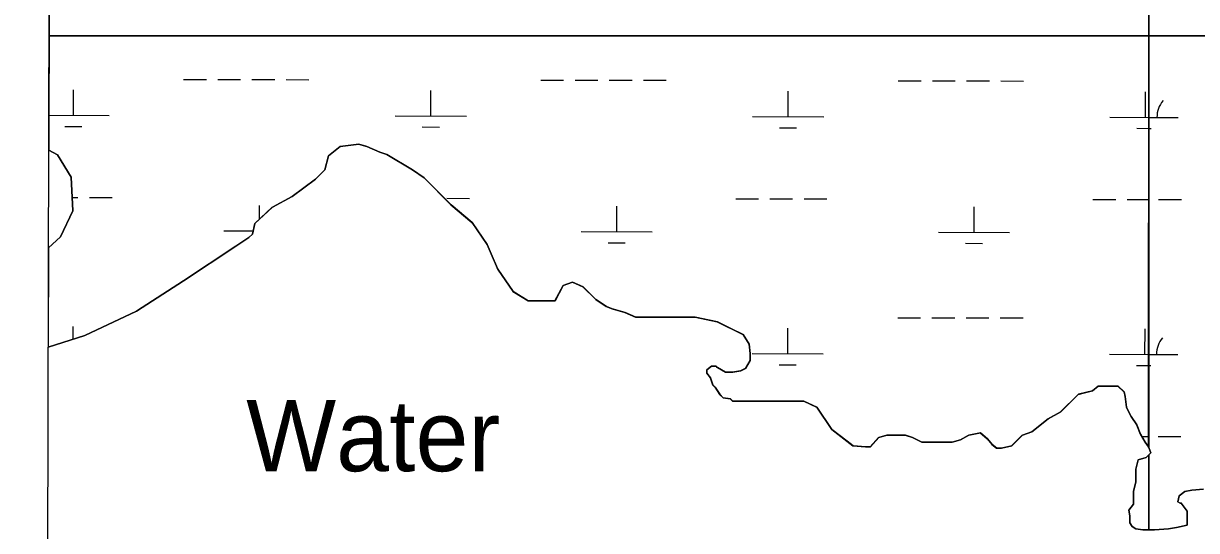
# Model space of a CAD drawing. Extents: x 3192952 to 3230831, y 849296 to 874698.
# Drawn here: x 3197144 to 3198792, y 869423 to 870134 of the extents above; entities that cross this region are included whole.
import ezdxf

# ---------------------------------------------------------------- set-up
doc = ezdxf.new("R2010")
doc.units = 0
for name, color, linetype in [('V-GRID-FRAM', 7, 'Continuous'), ('V-RIVR-IDEN', 7, 'Continuous'), ('V-SITE-VEGE', 7, 'Continuous'), ('V-TOPO-SHOR', 7, 'Continuous'), ('V-WETL-SWMP', 7, 'Continuous')]:
    doc.layers.add(name, color=color, linetype=linetype)

msp = doc.modelspace()

# ---------------------------------------------------------------- linework, layer by layer
at = {"layer": 'V-GRID-FRAM'}
msp.add_lwpolyline([(3197186.7, 872920.9), (3228554.1, 872861.6), (3228527.7, 854674), (3197144.3, 854733.3), (3197186.7, 872920.9)], dxfattribs=at)
at = {"layer": 'V-SITE-VEGE'}
for p, q in [((3197182.1, 870941.7), (3197180.1, 870116.9)), ((3197180.1, 870116.9), (3197179.8, 869956.4)), ((3197180.1, 870116.9), (3202799.6, 870116.9)), ((3199651, 870116.9), (3197180.1, 870116.9)), ((3197572.6, 869948.6), (3197589, 869961.7)), ((3197589, 869961.7), (3197615.3, 869965)), ((3197615.3, 869965), (3197626.8, 869961.7)), ((3197626.8, 869961.7), (3197644.8, 869953.5)), ((3197179.8, 869956.4), (3197192.1, 869950.1)), ((3197192.1, 869950.1), (3197211.1, 869918.7)), ((3197567.7, 869928.9), (3197572.6, 869948.6)), ((3197644.8, 869953.5), (3197654.7, 869950.2)), ((3197654.7, 869950.2), (3197690.8, 869928.9)), ((3197554.6, 869915.8), (3197567.7, 869928.9)), ((3197690.8, 869928.9), (3197707.2, 869917.4)), ((3197211.1, 869918.7), (3197213.6, 869871.1)), ((3197521.7, 869891.2), (3197554.6, 869915.8)), ((3197707.2, 869917.4), (3197744.9, 869879.7)), ((3197493.9, 869876.4), (3197521.7, 869891.2)), ((3197744.9, 869879.7), (3197774.4, 869855)), ((3197213.6, 869871.1), (3197196.4, 869834.9)), ((3197469.2, 869853.4), (3197493.9, 869876.4)), ((3197466, 869838.6), (3197469.2, 869853.4)), ((3197774.4, 869855), (3197795.8, 869823.9)), ((3197196.4, 869834.9), (3197179.4, 869819.4)), ((3197442.4, 869821.6), (3197461, 869833.7)), ((3197461, 869833.7), (3197466, 869838.6)), ((3197179.4, 869819.4), (3197179.1, 869680)), ((3197369.2, 869773.1), (3197442.4, 869821.6)), ((3197795.8, 869823.9), (3197804, 869804.2)), ((3197804, 869804.2), (3197810.5, 869789.4)), ((3197810.5, 869789.4), (3197831.9, 869758.2)), ((3197303.3, 869730.4), (3197369.2, 869773.1)), ((3197890.9, 869745.1), (3197902.4, 869766.4)), ((3197902.4, 869766.4), (3197915.6, 869771.3)), ((3197915.6, 869771.3), (3197930.3, 869764.8)), ((3197930.3, 869764.8), (3197948.4, 869746.7)), ((3197831.9, 869758.2), (3197853.2, 869745.1)), ((3197948.4, 869746.7), (3197963.1, 869736.9)), ((3197230.6, 869696.1), (3197303.3, 869730.4)), ((3197853.2, 869745.1), (3197890.9, 869745.1)), ((3197963.1, 869736.9), (3197971.3, 869733.6)), ((3197971.3, 869733.6), (3197989.4, 869728.7)), ((3197989.4, 869728.7), (3198004.2, 869722.1)), ((3198004.2, 869722.1), (3198087.8, 869722.1)), ((3198087.8, 869722.1), (3198119, 869715.5)), ((3198119, 869715.5), (3198155.1, 869697.5)), ((3197179.1, 869680), (3197230.6, 869696.1)), ((3198155.1, 869697.5), (3198163.3, 869684.3)), ((3198163.3, 869684.3), (3198165, 869671.2)), ((3198165, 869671.2), (3198165, 869661.4)), ((3198110.8, 869653.2), (3198104.3, 869648.2)), ((3198104.3, 869648.2), (3198104.3, 869643.3)), ((3198117.4, 869653.2), (3198110.8, 869653.2)), ((3198119, 869651.5), (3198117.4, 869653.2)), ((3198130.5, 869644.9), (3198119, 869651.5)), ((3198151.8, 869646.6), (3198140.4, 869644.9)), ((3198158.4, 869649.9), (3198151.8, 869646.6)), ((3198165, 869661.4), (3198158.4, 869649.9)), ((3198104.3, 869643.3), (3198109.2, 869636.7)), ((3198109.2, 869636.7), (3198112.5, 869626.9)), ((3198140.4, 869644.9), (3198130.5, 869644.9)), ((3198112.5, 869626.9), (3198115.7, 869623.6)), ((3198115.7, 869623.6), (3198122.3, 869613.8)), ((3198122.3, 869613.8), (3198127.2, 869608.8)), ((3198601.4, 869589.1), (3198626.1, 869613.8)), ((3198626.1, 869613.8), (3198645.7, 869618.7)), ((3198645.7, 869618.7), (3198653.9, 869625.2)), ((3198653.9, 869625.2), (3198681.8, 869625.2)), ((3198681.8, 869625.2), (3198690, 869617)), ((3198690, 869617), (3198691.7, 869610.5)), ((3198127.2, 869608.8), (3198137.1, 869607.2)), ((3198137.1, 869607.2), (3198140.4, 869603.9)), ((3198140.4, 869603.9), (3198240.4, 869603.9)), ((3198240.4, 869603.9), (3198258.5, 869595.7)), ((3198691.7, 869610.5), (3198693.3, 869595.7)), ((3198258.5, 869595.7), (3198265.1, 869585.9)), ((3198265.1, 869585.9), (3198273.3, 869574.4)), ((3198583.4, 869579.3), (3198601.4, 869589.1)), ((3198693.3, 869595.7), (3198699.9, 869582.6)), ((3198699.9, 869582.6), (3198708.1, 869571.1)), ((3198273.3, 869574.4), (3198279.8, 869564.5)), ((3198279.8, 869564.5), (3198301.2, 869548.1)), ((3198560.4, 869561.2), (3198583.4, 869579.3)), ((3198708.1, 869571.1), (3198713, 869557.9)), ((3198301.2, 869548.1), (3198309.4, 869541.5)), ((3198334, 869539.9), (3198345.5, 869553)), ((3198345.5, 869553), (3198357, 869556.3)), ((3198357, 869556.3), (3198383.2, 869556.3)), ((3198383.2, 869556.3), (3198393.1, 869553)), ((3198393.1, 869553), (3198406.2, 869546.5)), ((3198448.8, 869546.5), (3198460.3, 869549.7)), ((3198460.3, 869549.7), (3198471.8, 869556.3)), ((3198471.8, 869556.3), (3198488.2, 869559.6)), ((3198488.2, 869559.6), (3198498.1, 869551.4)), ((3198498.1, 869551.4), (3198504.6, 869543.2)), ((3198532.5, 869541.5), (3198547.3, 869556.3)), ((3198547.3, 869556.3), (3198560.4, 869561.2)), ((3198713, 869557.9), (3198719.6, 869546.5)), ((3198309.4, 869541.5), (3198327.4, 869539.9)), ((3198327.4, 869539.9), (3198334, 869539.9)), ((3198406.2, 869546.5), (3198448.8, 869546.5)), ((3198504.6, 869543.2), (3198511.2, 869538.3)), ((3198511.2, 869538.3), (3198517.8, 869538.3)), ((3198517.8, 869538.3), (3198532.5, 869541.5)), ((3198719.6, 869546.5), (3198724.5, 869539.9)), ((3198727.8, 869531.7), (3198721.2, 869525.1)), ((3198724.5, 869539.9), (3198727.8, 869531.7)), ((3198709.7, 869521.8), (3198706.5, 869508.7)), ((3198721.2, 869525.1), (3198709.7, 869521.8)), ((3198706.5, 869508.7), (3198706.5, 869490.7)), ((3198706.5, 869490.7), (3198703.2, 869477.5)), ((3198703.2, 869477.5), (3198703.2, 869459.5)), ((3198765.5, 869462.7), (3198767.2, 869471)), ((3198767.2, 869471), (3198775.4, 869477.5)), ((3198775.4, 869477.5), (3198785.2, 869479.2)), ((3198785.2, 869479.2), (3198801.6, 869480.8)), ((3198703.2, 869459.5), (3198696.6, 869451.3)), ((3198696.6, 869451.3), (3198698.3, 869443.1)), ((3198768.8, 869461.1), (3198765.5, 869462.7)), ((3198770.4, 869461.1), (3198768.8, 869461.1)), ((3198778.7, 869449.6), (3198770.4, 869461.1)), ((3198778.7, 869429.9), (3198778.7, 869449.6)), ((3198698.3, 869443.1), (3198698.3, 869433.2)), ((3198698.3, 869433.2), (3198701.5, 869428.3)), ((3198701.5, 869428.3), (3198706.5, 869425)), ((3198706.5, 869425), (3198716.3, 869423.4)), ((3198716.3, 869423.4), (3198732.7, 869423.4)), ((3198732.7, 869423.4), (3198752.4, 869425)), ((3198752.4, 869425), (3198763.9, 869426.6)), ((3198763.9, 869426.6), (3198778.7, 869429.9))]:
    msp.add_line(p, q, dxfattribs=at)
at = {"layer": 'V-TOPO-SHOR'}
for points in [[(3198046.8, 869722.1), (3198023.9, 869722.1), (3198004.2, 869722.1), (3197989.4, 869728.7), (3197971.3, 869733.6), (3197963.1, 869736.9), (3197948.4, 869746.7), (3197930.3, 869764.8), (3197915.6, 869771.3), (3197902.4, 869766.4), (3197890.9, 869745.1), (3197871.3, 869745.1), (3197853.2, 869745.1), (3197831.9, 869758.2), (3197810.5, 869789.4), (3197804, 869804.2), (3197795.8, 869823.9), (3197774.4, 869855), (3197744.9, 869879.7), (3197707.2, 869917.4), (3197690.8, 869928.9), (3197654.7, 869950.2), (3197644.8, 869953.5), (3197626.8, 869961.7), (3197615.3, 869965), (3197589, 869961.7), (3197572.6, 869948.6), (3197567.7, 869928.9), (3197554.6, 869915.8), (3197521.7, 869891.2), (3197493.9, 869876.4), (3197469.2, 869853.4), (3197466, 869838.6), (3197461, 869833.7), (3197442.4, 869821.6)], [(3197179.4, 869819.4), (3197196.4, 869834.9), (3197213.6, 869871.1), (3197211.1, 869918.7), (3197192.1, 869950.1), (3197179.8, 869956.4)], [(3197442.4, 869821.6), (3197369.2, 869773.1), (3197303.3, 869730.4), (3197230.6, 869696.1), (3197179.1, 869680)], [(3198785.2, 869479.2), (3198775.4, 869477.5), (3198767.2, 869471), (3198765.5, 869462.7), (3198768.8, 869461.1), (3198770.4, 869461.1), (3198778.7, 869449.6), (3198778.7, 869443.1), (3198778.7, 869429.9), (3198763.9, 869426.6), (3198752.4, 869425), (3198732.7, 869423.4), (3198716.3, 869423.4), (3198706.5, 869425), (3198701.5, 869428.3), (3198698.3, 869433.2), (3198698.3, 869443.1), (3198696.6, 869451.3), (3198703.2, 869459.5), (3198703.2, 869477.5), (3198706.5, 869490.7), (3198706.5, 869508.7), (3198709.7, 869521.8), (3198721.2, 869525.1), (3198727.8, 869531.7), (3198724.5, 869539.9), (3198719.6, 869546.5), (3198713, 869557.9), (3198708.1, 869571.1), (3198699.9, 869582.6), (3198693.3, 869595.7), (3198691.7, 869610.5), (3198690, 869617), (3198681.8, 869625.2), (3198673.6, 869625.2), (3198653.9, 869625.2), (3198645.7, 869618.7), (3198626.1, 869613.8), (3198601.4, 869589.1), (3198583.4, 869579.3), (3198560.4, 869561.2), (3198547.3, 869556.3), (3198532.5, 869541.5), (3198517.8, 869538.3), (3198511.2, 869538.3), (3198504.6, 869543.2), (3198498.1, 869551.4), (3198488.2, 869559.6), (3198471.8, 869556.3), (3198460.3, 869549.7), (3198448.8, 869546.5), (3198430.8, 869546.5), (3198417.7, 869546.5), (3198406.2, 869546.5), (3198393.1, 869553), (3198383.2, 869556.3), (3198366.8, 869556.3), (3198357, 869556.3), (3198345.5, 869553), (3198334, 869539.9), (3198327.4, 869539.9), (3198309.4, 869541.5), (3198301.2, 869548.1), (3198279.8, 869564.5), (3198273.3, 869574.4), (3198265.1, 869585.9), (3198258.5, 869595.7), (3198240.4, 869603.9), (3198230.6, 869603.9), (3198215.8, 869603.9), (3198204.3, 869603.9), (3198191.2, 869603.9), (3198183, 869603.9), (3198163.3, 869603.9), (3198156.8, 869603.9), (3198148.6, 869603.9), (3198140.4, 869603.9), (3198137.1, 869607.2), (3198127.2, 869608.8), (3198122.3, 869613.8), (3198115.7, 869623.6), (3198112.5, 869626.9), (3198109.2, 869636.7), (3198104.3, 869643.3), (3198104.3, 869648.2), (3198110.8, 869653.2), (3198117.4, 869653.2), (3198119, 869651.5), (3198130.5, 869644.9), (3198140.4, 869644.9), (3198151.8, 869646.6), (3198158.4, 869649.9), (3198165, 869661.4), (3198165, 869671.2), (3198163.3, 869684.3), (3198155.1, 869697.5), (3198138.7, 869705.7), (3198119, 869715.5), (3198087.8, 869722.1), (3198064.9, 869722.1), (3198046.8, 869722.1)], [(3198801.6, 869480.8), (3198785.2, 869479.2)]]:
    msp.add_lwpolyline(points, dxfattribs=at)
at = {"layer": 'V-WETL-SWMP'}
for p, q in [((3197182.1, 870941.7), (3197179.8, 869956.4)), ((3198724.4, 869538.9), (3198725.1, 870637.6)), ((3198724.9, 870637.5), (3198724.9, 869538.9)), ((3197369.2, 870055.8), (3197401.2, 870055.7)), ((3197417.2, 870055.7), (3197449.2, 870055.6)), ((3197465.2, 870055.6), (3197497.2, 870055.5)), ((3197513.2, 870055.5), (3197545.2, 870055.4)), ((3197871.1, 870054.8), (3197903, 870054.8)), ((3197919, 870054.7), (3197951, 870054.7)), ((3197967, 870054.6), (3197999, 870054.6)), ((3198015, 870054.6), (3198047, 870054.5)), ((3198372.9, 870053.9), (3198404.9, 870053.8)), ((3198420.9, 870053.8), (3198452.9, 870053.7)), ((3198468.9, 870053.7), (3198500.9, 870053.6)), ((3198516.9, 870053.6), (3198548.9, 870053.5)), ((3197214.6, 870005.3), (3197214.6, 870041.3)), ((3197716.4, 870004.4), (3197716.5, 870040.4)), ((3198218.2, 870003.4), (3198218.3, 870039.4)), ((3198720.1, 870002.5), (3198720.1, 870038.5)), ((3197179.9, 870005.4), (3197264.6, 870005.2)), ((3197666.4, 870004.5), (3197766.4, 870004.3)), ((3198168.2, 870003.5), (3198268.2, 870003.3)), ((3198670.1, 870002.6), (3198724.7, 870002.5)), ((3198724.9, 870002.5), (3198766.2, 870002.4)), ((3197202.5, 869989.9), (3197226.5, 869989.9)), ((3197704.4, 869989), (3197728.4, 869988.9)), ((3198206.2, 869988), (3198230.2, 869988)), ((3198708, 869987.1), (3198724.7, 869987)), ((3198724.9, 869987), (3198728.1, 869987)), ((3197572.5, 869948.6), (3197588.9, 869961.7)), ((3197588.9, 869961.7), (3197615.1, 869965)), ((3197615.1, 869965), (3197626.6, 869961.7)), ((3197626.6, 869961.7), (3197644.7, 869953.5)), ((3197179.8, 869956.4), (3197192.1, 869950.1)), ((3197192.1, 869950.1), (3197211, 869918.7)), ((3197567.6, 869928.9), (3197572.5, 869948.6)), ((3197644.7, 869953.5), (3197654.5, 869950.2)), ((3197654.5, 869950.2), (3197690.6, 869928.9)), ((3197554.4, 869915.8), (3197567.6, 869928.9)), ((3197690.6, 869928.9), (3197707, 869917.4)), ((3197211, 869918.7), (3197213.6, 869871.1)), ((3197521.6, 869891.2), (3197554.4, 869915.8)), ((3197707, 869917.4), (3197744.7, 869879.7)), ((3197212.6, 869889.9), (3197220.9, 869889.9)), ((3197236.9, 869889.9), (3197268.9, 869889.8)), ((3197475.7, 869859.5), (3197475.7, 869879)), ((3197493.7, 869876.4), (3197521.6, 869891.2)), ((3197738.8, 869888.9), (3197770.8, 869888.8)), ((3197744.7, 869879.7), (3197774.2, 869855)), ((3197977.5, 869842), (3197977.5, 869878)), ((3198144.6, 869888.1), (3198176.6, 869888.1)), ((3198192.6, 869888), (3198224.6, 869888)), ((3198240.6, 869888), (3198272.6, 869887.9)), ((3198646.4, 869887.2), (3198678.4, 869887.1)), ((3198694.4, 869887.1), (3198724.6, 869887)), ((3198738.5, 869887), (3198770.5, 869887)), ((3197213.6, 869871.1), (3197196.4, 869834.9)), ((3197469.1, 869853.4), (3197493.7, 869876.4)), ((3198479.3, 869841.1), (3198479.4, 869877.1)), ((3197465.9, 869838.6), (3197469.1, 869853.4)), ((3197774.2, 869855), (3197795.6, 869823.9)), ((3197196.4, 869834.9), (3197179.4, 869819.4)), ((3197425.7, 869843.1), (3197466.8, 869843)), ((3197442.3, 869821.6), (3197460.9, 869833.7)), ((3197460.9, 869833.7), (3197465.9, 869838.6)), ((3197927.5, 869842.1), (3198027.5, 869841.9)), ((3198429.3, 869841.2), (3198529.3, 869841)), ((3197179.4, 869819.4), (3197179.1, 869680)), ((3197369.1, 869773.1), (3197442.3, 869821.6)), ((3197795.6, 869823.9), (3197803.8, 869804.2)), ((3197965.5, 869826.6), (3197989.5, 869826.6)), ((3198467.3, 869825.7), (3198491.3, 869825.6)), ((3197803.8, 869804.2), (3197810.3, 869789.4)), ((3197810.3, 869789.4), (3197831.7, 869758.2)), ((3197303.3, 869730.4), (3197369.1, 869773.1)), ((3197890.7, 869745.1), (3197902.2, 869766.4)), ((3197902.2, 869766.4), (3197915.3, 869771.3)), ((3197915.3, 869771.3), (3197930.1, 869764.8)), ((3197930.1, 869764.8), (3197948.1, 869746.7)), ((3197831.7, 869758.2), (3197853, 869745.1)), ((3197948.1, 869746.7), (3197962.9, 869736.9)), ((3197230.6, 869696.1), (3197303.3, 869730.4)), ((3197853, 869745.1), (3197890.7, 869745.1)), ((3197962.9, 869736.9), (3197971.1, 869733.6)), ((3197971.1, 869733.6), (3197989.1, 869728.6)), ((3197989.1, 869728.6), (3198003.9, 869722.1)), ((3198003.9, 869722.1), (3198087.6, 869722.1)), ((3198087.6, 869722.1), (3198118.7, 869715.5)), ((3198118.7, 869715.5), (3198154.8, 869697.5)), ((3198372.3, 869721.2), (3198404.3, 869721.1)), ((3198420.3, 869721.1), (3198452.2, 869721.1)), ((3198468.2, 869721), (3198500.2, 869721)), ((3198516.2, 869720.9), (3198548.2, 869720.9)), ((3197179.1, 869680), (3197230.6, 869696.1)), ((3197214, 869690.9), (3197214, 869708.7)), ((3198154.8, 869697.5), (3198163, 869684.3)), ((3198217.6, 869670.8), (3198217.7, 869706.8)), ((3198719.4, 869669.8), (3198719.5, 869705.8)), ((3198163, 869684.3), (3198164.7, 869671.2)), ((3198164.7, 869671.2), (3198164.7, 869661.3)), ((3198167.6, 869670.9), (3198267.6, 869670.7)), ((3198669.4, 869669.9), (3198724.5, 869669.8)), ((3198724.9, 869669.8), (3198765.5, 869669.7)), ((3198110.5, 869653.1), (3198104, 869648.2)), ((3198104, 869648.2), (3198104, 869643.3)), ((3198117.1, 869653.1), (3198110.5, 869653.1)), ((3198118.7, 869651.5), (3198117.1, 869653.1)), ((3198130.2, 869644.9), (3198118.7, 869651.5)), ((3198151.5, 869646.6), (3198140, 869644.9)), ((3198158.1, 869649.9), (3198151.5, 869646.6)), ((3198164.7, 869661.3), (3198158.1, 869649.9)), ((3198205.6, 869655.3), (3198229.6, 869655.3)), ((3198707.4, 869654.4), (3198724.5, 869654.4)), ((3198724.9, 869654.4), (3198727.5, 869654.4)), ((3198104, 869643.3), (3198108.9, 869636.7)), ((3198108.9, 869636.7), (3198112.2, 869626.9)), ((3198140, 869644.9), (3198130.2, 869644.9)), ((3198112.2, 869626.9), (3198115.4, 869623.6)), ((3198115.4, 869623.6), (3198122, 869613.7)), ((3198122, 869613.7), (3198126.9, 869608.8)), ((3198601, 869589.1), (3198625.6, 869613.7)), ((3198625.6, 869613.7), (3198645.3, 869618.7)), ((3198645.3, 869618.7), (3198653.5, 869625.2)), ((3198653.5, 869625.2), (3198681.4, 869625.2)), ((3198681.4, 869625.2), (3198689.6, 869617)), ((3198689.6, 869617), (3198691.2, 869610.5)), ((3198126.9, 869608.8), (3198136.8, 869607.2)), ((3198136.8, 869607.2), (3198140, 869603.9)), ((3198140, 869603.9), (3198240.1, 869603.9)), ((3198240.1, 869603.9), (3198258.2, 869595.7)), ((3198691.2, 869610.5), (3198692.9, 869595.7)), ((3198258.2, 869595.7), (3198264.7, 869585.8)), ((3198264.7, 869585.8), (3198272.9, 869574.4)), ((3198582.9, 869579.3), (3198601, 869589.1)), ((3198692.9, 869595.7), (3198699.4, 869582.6)), ((3198699.4, 869582.6), (3198707.6, 869571.1)), ((3198272.9, 869574.4), (3198279.5, 869564.5)), ((3198279.5, 869564.5), (3198300.8, 869548.1)), ((3198560, 869561.2), (3198582.9, 869579.3)), ((3198707.6, 869571.1), (3198712.5, 869557.9)), ((3198300.8, 869548.1), (3198309, 869541.5)), ((3198333.6, 869539.9), (3198345.1, 869553)), ((3198345.1, 869553), (3198356.6, 869556.3)), ((3198356.6, 869556.3), (3198382.8, 869556.3)), ((3198382.8, 869556.3), (3198392.7, 869553)), ((3198392.7, 869553), (3198405.8, 869546.4)), ((3198448.4, 869546.4), (3198459.9, 869549.7)), ((3198459.9, 869549.7), (3198471.4, 869556.3)), ((3198471.4, 869556.3), (3198487.8, 869559.6)), ((3198487.8, 869559.6), (3198497.7, 869551.4)), ((3198497.7, 869551.4), (3198504.2, 869543.2)), ((3198532.1, 869541.5), (3198546.9, 869556.3)), ((3198546.9, 869556.3), (3198560, 869561.2)), ((3198712.5, 869557.9), (3198719.1, 869546.4)), ((3198714.6, 869554.4), (3198724.4, 869554.4)), ((3198737.9, 869554.3), (3198769.9, 869554.3)), ((3198309, 869541.5), (3198327.1, 869539.9)), ((3198327.1, 869539.9), (3198333.6, 869539.9)), ((3198405.8, 869546.4), (3198448.4, 869546.4)), ((3198504.2, 869543.2), (3198510.8, 869538.2)), ((3198510.8, 869538.2), (3198517.3, 869538.2)), ((3198517.3, 869538.2), (3198532.1, 869541.5)), ((3198719.1, 869546.4), (3198724, 869539.9)), ((3198724, 869539.9), (3198724.4, 869538.9)), ((3198724.9, 869538.9), (3198727.8, 869531.7)), ((3198727.8, 869531.7), (3198724.9, 869528.8)), ((3198724.9, 869528.8), (3198724.9, 869423.4)), ((3198765.5, 869462.7), (3198767.2, 869471)), ((3198767.2, 869471), (3198775.4, 869477.5)), ((3198775.4, 869477.5), (3198785.2, 869479.2)), ((3198785.2, 869479.2), (3198801.6, 869480.8)), ((3198768.8, 869461.1), (3198765.5, 869462.7)), ((3198770.5, 869461.1), (3198768.8, 869461.1)), ((3198778.7, 869449.6), (3198770.5, 869461.1)), ((3198778.7, 869429.9), (3198778.7, 869449.6)), ((3198724.9, 869423.4), (3198732.7, 869423.4)), ((3198732.7, 869423.4), (3198752.4, 869425)), ((3198752.4, 869425), (3198763.9, 869426.6)), ((3198763.9, 869426.6), (3198778.7, 869429.9))]:
    msp.add_line(p, q, dxfattribs=at)
msp.add_lwpolyline([(3198724.9, 869423.4), (3198724.9, 869528.8), (3198721.2, 869525.1), (3198709.7, 869521.8), (3198706.5, 869508.7), (3198706.5, 869490.7), (3198703.2, 869477.5), (3198703.2, 869459.5), (3198696.6, 869451.3), (3198698.3, 869443.1), (3198698.3, 869433.2), (3198701.5, 869428.3), (3198706.5, 869425), (3198716.3, 869423.4)], close=True, dxfattribs=at)
for centre in [(3198771.4, 870002.9), (3198770.8, 869670.2)]:
    msp.add_arc(centre, 35.2, 139.1198, 180.6635, dxfattribs=at)

# ---------------------------------------------------------------- texts
at = {"layer": 'V-RIVR-IDEN'}
msp.add_text('Water', height=100, dxfattribs=at).set_placement((3197457.2, 869505.8))

doc.saveas('drawing.dxf')
